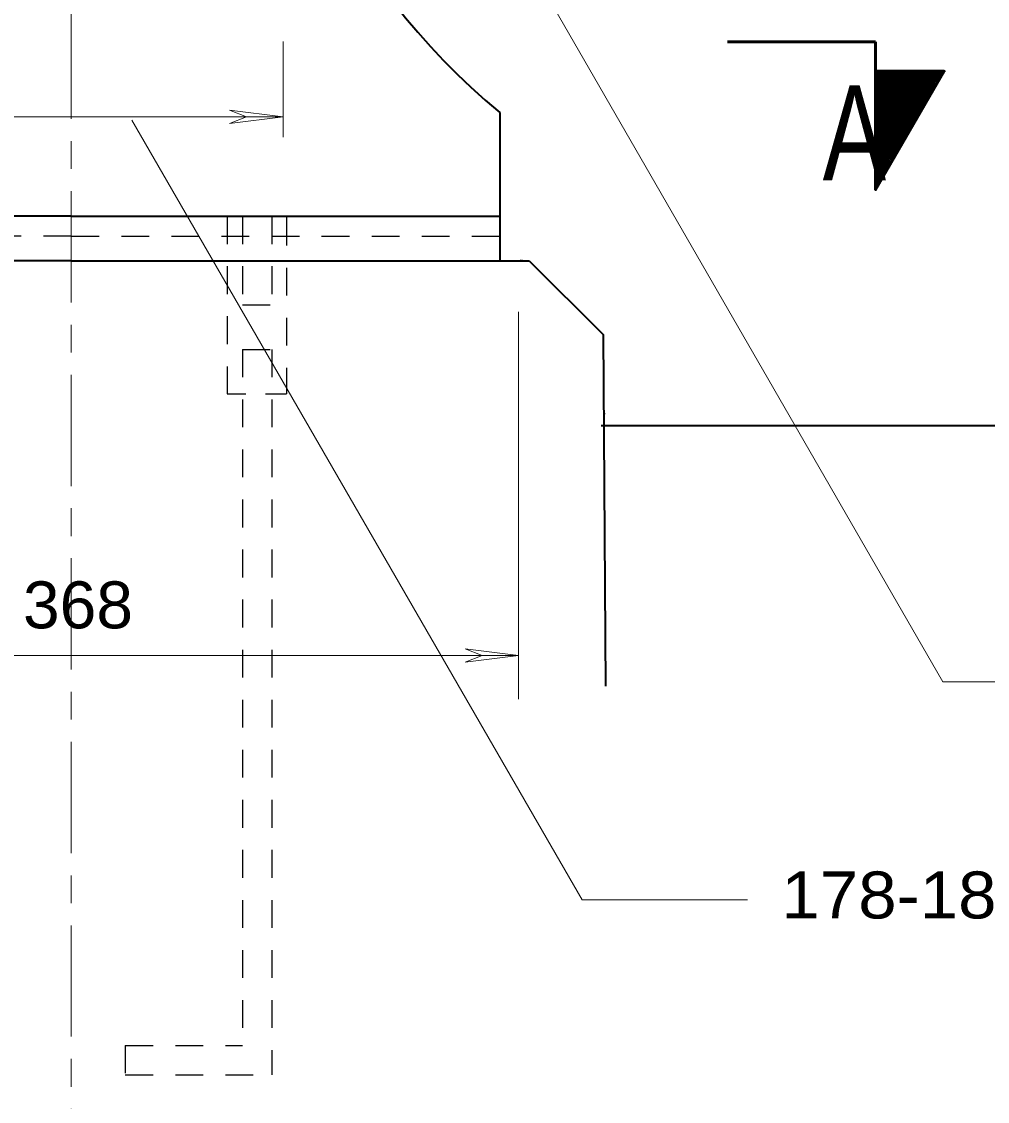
# Model space of a CAD drawing. Extents: x 312583 to 312854, y 144419 to 144597.
# Drawn here: x 312639.27 to 312654.89, y 144437.86 to 144455.33 of the extents above; entities that cross this region are included whole.
import ezdxf
from ezdxf.enums import TextEntityAlignment as Align

# ---------------------------------------------------------------- set-up
doc = ezdxf.new("R2010")
doc.units = 0
doc.header["$LTSCALE"] = 0.3
doc.linetypes.add('LONG_DASH_SHORT_DASH', pattern=[9.9, 6, -1.2, 1.5, -1.2])
doc.linetypes.add('SHORT_DASHED', pattern=[2.7, 1.5, -1.2])
doc.layers.add('1', color=7, linetype='Continuous', lineweight=40)
doc.layers.add('2', color=7, linetype='Continuous', lineweight=13)

msp = doc.modelspace()

# ---------------------------------------------------------------- linework, layer by layer
at = {"layer": '1', "linetype": 'LONG_DASH_SHORT_DASH', "lineweight": 13}
msp.add_line((312640.0738, 144435.9326), (312640.0738, 144549.4913), dxfattribs=at)
at = {"layer": '1'}
for p, q in [((312647.0045, 144453.8573), (312647.0045, 144451.4576)), ((312647.0045, 144453.8573), (312647.0045, 144451.4576)), ((312647.0045, 144453.8573), (312647.0045, 144451.4576)), ((312647.0045, 144453.8573), (312647.0045, 144451.4576)), ((312647.0045, 144453.8573), (312647.0045, 144451.4576)), ((312647.0045, 144453.8573), (312647.0045, 144451.4576)), ((312647.0045, 144453.8573), (312647.0045, 144451.4576)), ((312647.0045, 144453.8573), (312647.0045, 144451.4576)), ((312640.0738, 144452.1783), (312633.1432, 144452.1783)), ((312640.0738, 144452.1783), (312633.1432, 144452.1783)), ((312640.0738, 144452.1783), (312633.1432, 144452.1783)), ((312640.0738, 144452.1783), (312633.1432, 144452.1783)), ((312640.0738, 144452.1783), (312633.1432, 144452.1783)), ((312640.0738, 144452.1783), (312633.1432, 144452.1783)), ((312640.0738, 144452.1783), (312633.1432, 144452.1783)), ((312640.0738, 144452.1783), (312633.1432, 144452.1783)), ((312640.0738, 144452.1783), (312647.0045, 144452.1783)), ((312640.0738, 144452.1783), (312647.0045, 144452.1783)), ((312640.0738, 144452.1783), (312647.0045, 144452.1783)), ((312640.0738, 144452.1783), (312647.0045, 144452.1783)), ((312640.0738, 144452.1783), (312647.0045, 144452.1783)), ((312640.0738, 144452.1783), (312647.0045, 144452.1783)), ((312640.0738, 144452.1783), (312647.0045, 144452.1783)), ((312640.0738, 144452.1783), (312647.0045, 144452.1783)), ((312640.0738, 144451.4576), (312632.6755, 144451.4576)), ((312640.0738, 144451.4576), (312632.6755, 144451.4576)), ((312640.0738, 144451.4576), (312632.6755, 144451.4576)), ((312640.0738, 144451.4576), (312632.6755, 144451.4576)), ((312640.0738, 144451.4576), (312632.6755, 144451.4576)), ((312640.0738, 144451.4576), (312632.6755, 144451.4576)), ((312640.0738, 144451.4576), (312632.6755, 144451.4576)), ((312640.0738, 144451.4576), (312632.6755, 144451.4576)), ((312640.0738, 144451.4576), (312647.4798, 144451.4576)), ((312640.0738, 144451.4576), (312647.4798, 144451.4576)), ((312640.0738, 144451.4576), (312647.4798, 144451.4576)), ((312640.0738, 144451.4576), (312647.4798, 144451.4576)), ((312640.0738, 144451.4576), (312647.4798, 144451.4576)), ((312640.0738, 144451.4576), (312647.4798, 144451.4576)), ((312640.0738, 144451.4576), (312647.4798, 144451.4576)), ((312640.0738, 144451.4576), (312647.4798, 144451.4576)), ((312647.3495, 144451.4576), (312647.3418, 144451.4653)), ((312647.3495, 144451.4576), (312647.3418, 144451.4653)), ((312647.3495, 144451.4576), (312647.3418, 144451.4653)), ((312647.3495, 144451.4576), (312647.3418, 144451.4653)), ((312647.3495, 144451.4576), (312647.3418, 144451.4653)), ((312647.3495, 144451.4576), (312647.3418, 144451.4653)), ((312647.3495, 144451.4576), (312647.3418, 144451.4653)), ((312647.3495, 144451.4576), (312647.3418, 144451.4653)), ((312647.3725, 144451.4576), (312647.3648, 144451.4576)), ((312647.3725, 144451.4576), (312647.3648, 144451.4576)), ((312647.3725, 144451.4576), (312647.3648, 144451.4576)), ((312647.3725, 144451.4576), (312647.3648, 144451.4576)), ((312647.3725, 144451.4576), (312647.3648, 144451.4576)), ((312647.3725, 144451.4576), (312647.3648, 144451.4576)), ((312647.3725, 144451.4576), (312647.3648, 144451.4576)), ((312647.3725, 144451.4576), (312647.3648, 144451.4576)), ((312647.3725, 144451.4576), (312647.3648, 144451.4576)), ((312647.3725, 144451.4576), (312647.3648, 144451.4576)), ((312647.3725, 144451.4576), (312647.3648, 144451.4576)), ((312647.3725, 144451.4576), (312647.3648, 144451.4576)), ((312647.3725, 144451.4576), (312647.3648, 144451.4576)), ((312647.3725, 144451.4576), (312647.3648, 144451.4576)), ((312647.3725, 144451.4576), (312647.3648, 144451.4576)), ((312647.3725, 144451.4576), (312647.3648, 144451.4576)), ((312647.4798, 144451.4576), (312648.6758, 144450.2616)), ((312647.4798, 144451.4576), (312648.6758, 144450.2616)), ((312647.4798, 144451.4576), (312648.6758, 144450.2616)), ((312647.4798, 144451.4576), (312648.6758, 144450.2616)), ((312647.4798, 144451.4576), (312648.6758, 144450.2616)), ((312647.4798, 144451.4576), (312648.6758, 144450.2616)), ((312647.4798, 144451.4576), (312648.6758, 144450.2616)), ((312647.4798, 144451.4576), (312648.6758, 144450.2616)), ((312648.6758, 144450.2616), (312648.7142, 144444.5729)), ((312648.6758, 144450.2616), (312648.7142, 144444.5729)), ((312648.6758, 144450.2616), (312648.7142, 144444.5729)), ((312648.6758, 144450.2616), (312648.7142, 144444.5729)), ((312648.6758, 144450.2616), (312648.7142, 144444.5729)), ((312648.6758, 144450.2616), (312648.7142, 144444.5729)), ((312648.6758, 144450.2616), (312648.7142, 144444.5729)), ((312648.6758, 144450.2616), (312648.7142, 144444.5729)), ((312648.6988, 144448.9813), (312648.7065, 144448.9736)), ((312648.6988, 144448.9813), (312648.7065, 144448.9736)), ((312648.6988, 144448.9813), (312648.7065, 144448.9736)), ((312648.6988, 144448.9813), (312648.7065, 144448.9736)), ((312648.6988, 144448.9813), (312648.7065, 144448.9736)), ((312648.6988, 144448.9813), (312648.7065, 144448.9736)), ((312648.6988, 144448.9813), (312648.7065, 144448.9736)), ((312648.6988, 144448.9813), (312648.7065, 144448.9736)), ((312648.6452, 144448.7896), (312660.3062, 144448.7896)), ((312648.6452, 144448.7896), (312660.3062, 144448.7896)), ((312648.6452, 144448.7896), (312660.3062, 144448.7896)), ((312648.6452, 144448.7896), (312660.3062, 144448.7896)), ((312648.6452, 144448.7896), (312660.3062, 144448.7896)), ((312648.6452, 144448.7896), (312660.3062, 144448.7896)), ((312648.6452, 144448.7896), (312660.3062, 144448.7896)), ((312648.6452, 144448.7896), (312660.3062, 144448.7896))]:
    msp.add_line(p, q, dxfattribs=at)
at = {"layer": '1', "linetype": 'SHORT_DASHED', "lineweight": 25}
for p, q in [((312642.5962, 144452.1783), (312642.5962, 144449.3033)), ((312642.5962, 144452.1783), (312642.5962, 144449.3033)), ((312642.5962, 144452.1783), (312642.5962, 144449.3033)), ((312642.5962, 144452.1783), (312642.5962, 144449.3033)), ((312642.5962, 144452.1783), (312642.5962, 144449.3033)), ((312642.5962, 144452.1783), (312642.5962, 144449.3033)), ((312642.5962, 144452.1783), (312642.5962, 144449.3033)), ((312642.5962, 144452.1783), (312642.5962, 144449.3033)), ((312642.8415, 144452.1783), (312642.8415, 144450.7446)), ((312642.8415, 144452.1783), (312642.8415, 144450.7446)), ((312642.8415, 144452.1783), (312642.8415, 144450.7446)), ((312642.8415, 144452.1783), (312642.8415, 144450.7446)), ((312642.8415, 144452.1783), (312642.8415, 144450.7446)), ((312642.8415, 144452.1783), (312642.8415, 144450.7446)), ((312642.8415, 144452.1783), (312642.8415, 144450.7446)), ((312642.8415, 144452.1783), (312642.8415, 144450.7446)), ((312643.3168, 144452.1783), (312643.3168, 144450.7446)), ((312643.3168, 144452.1783), (312643.3168, 144450.7446)), ((312643.3168, 144452.1783), (312643.3168, 144450.7446)), ((312643.3168, 144452.1783), (312643.3168, 144450.7446)), ((312643.3168, 144452.1783), (312643.3168, 144450.7446)), ((312643.3168, 144452.1783), (312643.3168, 144450.7446)), ((312643.3168, 144452.1783), (312643.3168, 144450.7446)), ((312643.3168, 144452.1783), (312643.3168, 144450.7446)), ((312643.5545, 144452.1553), (312643.5545, 144449.3033)), ((312643.5545, 144452.1553), (312643.5545, 144449.3033)), ((312643.5545, 144452.1553), (312643.5545, 144449.3033)), ((312643.5545, 144452.1553), (312643.5545, 144449.3033)), ((312643.5545, 144452.1553), (312643.5545, 144449.3033)), ((312643.5545, 144452.1553), (312643.5545, 144449.3033)), ((312643.5545, 144452.1553), (312643.5545, 144449.3033)), ((312643.5545, 144452.1553), (312643.5545, 144449.3033)), ((312640.0738, 144451.8563), (312633.1432, 144451.8563)), ((312640.0738, 144451.8563), (312633.1432, 144451.8563)), ((312640.0738, 144451.8563), (312633.1432, 144451.8563)), ((312640.0738, 144451.8563), (312633.1432, 144451.8563)), ((312640.0738, 144451.8563), (312633.1432, 144451.8563)), ((312640.0738, 144451.8563), (312633.1432, 144451.8563)), ((312640.0738, 144451.8563), (312633.1432, 144451.8563)), ((312640.0738, 144451.8563), (312633.1432, 144451.8563)), ((312640.0738, 144451.8563), (312647.0045, 144451.8563)), ((312640.0738, 144451.8563), (312647.0045, 144451.8563)), ((312640.0738, 144451.8563), (312647.0045, 144451.8563)), ((312640.0738, 144451.8563), (312647.0045, 144451.8563)), ((312640.0738, 144451.8563), (312647.0045, 144451.8563)), ((312640.0738, 144451.8563), (312647.0045, 144451.8563)), ((312640.0738, 144451.8563), (312647.0045, 144451.8563)), ((312640.0738, 144451.8563), (312647.0045, 144451.8563)), ((312642.8415, 144450.7446), (312643.3168, 144450.7446)), ((312642.8415, 144450.7446), (312643.3168, 144450.7446)), ((312642.8415, 144450.7446), (312643.3168, 144450.7446)), ((312642.8415, 144450.7446), (312643.3168, 144450.7446)), ((312642.8415, 144450.7446), (312643.3168, 144450.7446)), ((312642.8415, 144450.7446), (312643.3168, 144450.7446)), ((312642.8415, 144450.7446), (312643.3168, 144450.7446)), ((312642.8415, 144450.7446), (312643.3168, 144450.7446)), ((312642.8415, 144450.0239), (312643.3168, 144450.0239)), ((312642.8415, 144450.0239), (312642.8415, 144438.7616)), ((312642.8415, 144450.0239), (312643.3168, 144450.0239)), ((312642.8415, 144450.0239), (312642.8415, 144438.7616)), ((312642.8415, 144450.0239), (312643.3168, 144450.0239)), ((312642.8415, 144450.0239), (312642.8415, 144438.7616)), ((312642.8415, 144450.0239), (312643.3168, 144450.0239)), ((312642.8415, 144450.0239), (312642.8415, 144438.7616)), ((312642.8415, 144450.0239), (312643.3168, 144450.0239)), ((312642.8415, 144450.0239), (312642.8415, 144438.7616)), ((312642.8415, 144450.0239), (312643.3168, 144450.0239)), ((312642.8415, 144450.0239), (312642.8415, 144438.7616)), ((312642.8415, 144450.0239), (312643.3168, 144450.0239)), ((312642.8415, 144450.0239), (312642.8415, 144438.7616)), ((312642.8415, 144450.0239), (312643.3168, 144450.0239)), ((312642.8415, 144450.0239), (312642.8415, 144438.7616)), ((312643.3168, 144450.0239), (312643.3168, 144438.2863)), ((312643.3168, 144450.0239), (312643.3168, 144438.2863)), ((312643.3168, 144450.0239), (312643.3168, 144438.2863)), ((312643.3168, 144450.0239), (312643.3168, 144438.2863)), ((312643.3168, 144450.0239), (312643.3168, 144438.2863)), ((312643.3168, 144450.0239), (312643.3168, 144438.2863)), ((312643.3168, 144450.0239), (312643.3168, 144438.2863)), ((312643.3168, 144450.0239), (312643.3168, 144438.2863)), ((312642.5962, 144449.3033), (312642.8952, 144449.3033)), ((312642.5962, 144449.3033), (312642.8952, 144449.3033)), ((312642.5962, 144449.3033), (312642.8952, 144449.3033)), ((312642.5962, 144449.3033), (312642.8952, 144449.3033)), ((312642.5962, 144449.3033), (312642.8952, 144449.3033)), ((312642.5962, 144449.3033), (312642.8952, 144449.3033)), ((312642.5962, 144449.3033), (312642.8952, 144449.3033)), ((312642.5962, 144449.3033), (312642.8952, 144449.3033)), ((312643.2172, 144449.3033), (312643.5545, 144449.3033)), ((312643.2172, 144449.3033), (312643.5545, 144449.3033)), ((312643.2172, 144449.3033), (312643.5545, 144449.3033)), ((312643.2172, 144449.3033), (312643.5545, 144449.3033)), ((312643.2172, 144449.3033), (312643.5545, 144449.3033)), ((312643.2172, 144449.3033), (312643.5545, 144449.3033)), ((312643.2172, 144449.3033), (312643.5545, 144449.3033)), ((312643.2172, 144449.3033), (312643.5545, 144449.3033)), ((312640.9478, 144438.7616), (312642.8415, 144438.7616)), ((312640.9478, 144438.7616), (312640.9478, 144438.2863)), ((312640.9478, 144438.7616), (312642.8415, 144438.7616)), ((312640.9478, 144438.7616), (312640.9478, 144438.2863)), ((312640.9478, 144438.7616), (312642.8415, 144438.7616)), ((312640.9478, 144438.7616), (312640.9478, 144438.2863)), ((312640.9478, 144438.7616), (312642.8415, 144438.7616)), ((312640.9478, 144438.7616), (312640.9478, 144438.2863)), ((312640.9478, 144438.7616), (312642.8415, 144438.7616)), ((312640.9478, 144438.7616), (312640.9478, 144438.2863)), ((312640.9478, 144438.7616), (312642.8415, 144438.7616)), ((312640.9478, 144438.7616), (312640.9478, 144438.2863)), ((312640.9478, 144438.7616), (312642.8415, 144438.7616)), ((312640.9478, 144438.7616), (312640.9478, 144438.2863)), ((312640.9478, 144438.7616), (312642.8415, 144438.7616)), ((312640.9478, 144438.7616), (312640.9478, 144438.2863)), ((312640.9478, 144438.2863), (312643.3168, 144438.2863)), ((312640.9478, 144438.2863), (312643.3168, 144438.2863)), ((312640.9478, 144438.2863), (312643.3168, 144438.2863)), ((312640.9478, 144438.2863), (312643.3168, 144438.2863)), ((312640.9478, 144438.2863), (312643.3168, 144438.2863)), ((312640.9478, 144438.2863), (312643.3168, 144438.2863)), ((312640.9478, 144438.2863), (312643.3168, 144438.2863)), ((312640.9478, 144438.2863), (312643.3168, 144438.2863))]:
    msp.add_line(p, q, dxfattribs=at)
at = {"layer": '1'}
msp.add_arc((312654.0635, 144462.3949), 11.0776, 179.55818, 230.43377, dxfattribs=at)
msp.add_arc((312654.0635, 144462.3949), 11.0776, 179.55818, 230.43377, dxfattribs=at)
msp.add_arc((312654.0635, 144462.3949), 11.0776, 179.55818, 230.43377, dxfattribs=at)
msp.add_arc((312654.0635, 144462.3949), 11.0776, 179.55818, 230.43377, dxfattribs=at)
msp.add_arc((312654.0635, 144462.3949), 11.0776, 179.55818, 230.43377, dxfattribs=at)
msp.add_arc((312654.0635, 144462.3949), 11.0776, 179.55818, 230.43377, dxfattribs=at)
msp.add_arc((312654.0635, 144462.3949), 11.0776, 179.55818, 230.43377, dxfattribs=at)
msp.add_arc((312654.0635, 144462.3949), 11.0776, 179.55818, 230.43377, dxfattribs=at)
at = {"layer": '2'}
for p, q in [((312647.7865, 144455.7203), (312654.1728, 144444.6419)), ((312643.5008, 144455.0073), (312643.5008, 144453.4586)), ((312642.6345, 144453.8956), (312642.9105, 144453.7883)), ((312643.5008, 144453.7883), (312642.6345, 144453.8956)), ((312636.8155, 144453.7883), (312643.5008, 144453.7883)), ((312641.0552, 144453.7346), (312648.3385, 144441.1153)), ((312642.6345, 144453.6809), (312642.9105, 144453.7883)), ((312643.5008, 144453.7883), (312642.6345, 144453.6809)), ((312647.3112, 144444.3659), (312647.3112, 144450.6296)), ((312647.3112, 144445.0713), (312633.0895, 144445.0713)), ((312646.4448, 144445.1786), (312646.7208, 144445.0713)), ((312647.3112, 144445.0713), (312646.4448, 144445.1786)), ((312646.4448, 144444.9639), (312646.7208, 144445.0713)), ((312647.3112, 144445.0713), (312646.4448, 144444.9639)), ((312657.8222, 144444.6419), (312654.1728, 144444.6419)), ((312651.0108, 144441.1153), (312648.3385, 144441.1153))]:
    msp.add_line(p, q, dxfattribs=at)
at = {"layer": '2', "lineweight": 53}
for p in [(312650.6922, 144454.9996), (312653.0842, 144454.5243)]:
    msp.add_line(p, (312653.0842, 144454.9996), dxfattribs=at)
at = {"layer": '2', "lineweight": 35}
for p, q in [((312653.0842, 144454.5089), (312653.9045, 144454.0336)), ((312653.1072, 144454.5243), (312653.9198, 144454.0489)), ((312653.1608, 144454.5243), (312653.9275, 144454.0796)), ((312653.1992, 144454.5243), (312653.9428, 144454.0949)), ((312653.2528, 144454.5243), (312653.9505, 144454.1179)), ((312653.2988, 144454.5243), (312653.9658, 144454.1409)), ((312653.3448, 144454.5243), (312653.9812, 144454.1563)), ((312653.3908, 144454.5243), (312653.9888, 144454.1793)), ((312653.4445, 144454.5243), (312654.0042, 144454.2023)), ((312653.4905, 144454.5243), (312654.0195, 144454.2176)), ((312653.5365, 144454.5243), (312654.0272, 144454.2406)), ((312653.5902, 144454.5243), (312654.0425, 144454.2559)), ((312653.6362, 144454.5243), (312654.0502, 144454.2789)), ((312653.6822, 144454.5243), (312654.0655, 144454.3019)), ((312653.7358, 144454.5243), (312654.0732, 144454.3173)), ((312653.7818, 144454.5243), (312654.0885, 144454.3479)), ((312653.8278, 144454.5243), (312654.0962, 144454.3633)), ((312653.8738, 144454.5243), (312654.1115, 144454.3863)), ((312653.9275, 144454.5243), (312654.1192, 144454.4093)), ((312653.9658, 144454.5243), (312654.1345, 144454.4246)), ((312654.0195, 144454.5243), (312654.1422, 144454.4476)), ((312654.0655, 144454.5243), (312654.1575, 144454.4706)), ((312654.1192, 144454.5243), (312654.1728, 144454.4859)), ((312654.1652, 144454.5243), (312654.1805, 144454.5089)), ((312653.0842, 144454.4783), (312653.8968, 144454.0106)), ((312653.0842, 144454.4476), (312653.8815, 144453.9876)), ((312653.0842, 144454.4246), (312653.8738, 144453.9723)), ((312653.0842, 144454.3939), (312653.8585, 144453.9493)), ((312653.0918, 144454.3709), (312653.8508, 144453.9263)), ((312653.0918, 144454.3403), (312653.8355, 144453.9109)), ((312653.0842, 144454.3173), (312653.8278, 144453.8879)), ((312653.0842, 144454.2866), (312653.8125, 144453.8649)), ((312653.0842, 144454.2559), (312653.7972, 144453.8496)), ((312653.0842, 144454.2329), (312653.7895, 144453.8266)), ((312653.0842, 144454.2023), (312653.7742, 144453.8036)), ((312653.0842, 144454.1716), (312653.7588, 144453.7806)), ((312653.0842, 144454.1486), (312653.7512, 144453.7653)), ((312653.0842, 144454.0873), (312653.7282, 144453.7193)), ((312653.0842, 144454.0643), (312653.7128, 144453.7039)), ((312653.0842, 144454.0413), (312653.7052, 144453.6809)), ((312653.0842, 144454.0106), (312653.6898, 144453.6579)), ((312653.0842, 144453.9799), (312653.6822, 144453.6426)), ((312653.0918, 144454.1179), (312653.7358, 144453.7423)), ((312653.0842, 144453.9493), (312653.6668, 144453.6196)), ((312653.0842, 144453.9263), (312653.6592, 144453.5966)), ((312653.0842, 144453.8956), (312653.6438, 144453.5813)), ((312653.0842, 144453.8419), (312653.6208, 144453.5353)), ((312653.0842, 144453.8189), (312653.6055, 144453.5123)), ((312653.0918, 144453.8726), (312653.6362, 144453.5506)), ((312653.0842, 144453.7883), (312653.5978, 144453.4893)), ((312653.0842, 144453.7576), (312653.5825, 144453.4739)), ((312653.0842, 144453.7346), (312653.5748, 144453.4509)), ((312653.0842, 144453.7039), (312653.5595, 144453.4279)), ((312653.0842, 144453.6733), (312653.5518, 144453.4126)), ((312653.0842, 144453.6503), (312653.5365, 144453.3896)), ((312653.0842, 144453.6196), (312653.5288, 144453.3666)), ((312653.0842, 144453.5889), (312653.5135, 144453.3513)), ((312653.0842, 144453.5659), (312653.5058, 144453.3283)), ((312653.0842, 144453.5429), (312653.4905, 144453.3053)), ((312653.0842, 144453.5123), (312653.4828, 144453.2823)), ((312653.0842, 144453.4816), (312653.4675, 144453.2669)), ((312653.0842, 144453.4509), (312653.4522, 144453.2439)), ((312653.0842, 144453.4279), (312653.4445, 144453.2209)), ((312653.0842, 144453.3973), (312653.4292, 144453.2056)), ((312653.0842, 144453.3743), (312653.4138, 144453.1826)), ((312653.0842, 144453.3436), (312653.4062, 144453.1596)), ((312653.0842, 144453.3206), (312653.3908, 144453.1443)), ((312653.0842, 144453.2899), (312653.3832, 144453.1213)), ((312653.0842, 144453.2593), (312653.3678, 144453.0983)), ((312653.0842, 144453.2363), (312653.3602, 144453.0829)), ((312653.0842, 144453.2056), (312653.3448, 144453.0523)), ((312653.0842, 144453.1826), (312653.3372, 144453.0369)), ((312653.0842, 144453.1519), (312653.3218, 144453.0139)), ((312653.0842, 144453.1213), (312653.3142, 144452.9909)), ((312653.0842, 144453.0983), (312653.2988, 144452.9756)), ((312653.0842, 144453.0676), (312653.2912, 144452.9526)), ((312653.0842, 144453.0446), (312653.2758, 144452.9296)), ((312653.0842, 144453.0139), (312653.2605, 144452.9143)), ((312653.0842, 144452.9833), (312653.2528, 144452.8913)), ((312653.0842, 144452.9526), (312653.2375, 144452.8683)), ((312653.0842, 144452.9296), (312653.2222, 144452.8529)), ((312653.0842, 144452.8989), (312653.2145, 144452.8299)), ((312653.0842, 144452.8759), (312653.1992, 144452.8069)), ((312653.0842, 144452.8529), (312653.1915, 144452.7839)), ((312653.0842, 144452.8223), (312653.1762, 144452.7686)), ((312653.0842, 144452.7916), (312653.1685, 144452.7456)), ((312653.0842, 144452.7609), (312653.1532, 144452.7226)), ((312653.0842, 144452.7379), (312653.1455, 144452.7073)), ((312653.0842, 144452.7073), (312653.1302, 144452.6843)), ((312653.0842, 144452.6843), (312653.1225, 144452.6613)), ((312653.0842, 144452.6536), (312653.1072, 144452.6459)), ((312653.0842, 144452.6229), (312653.0995, 144452.6229))]:
    msp.add_line(p, q, dxfattribs=at)
at = {"layer": '2', "lineweight": 53}
msp.add_lwpolyline([(312653.0842, 144454.5243), (312654.1958, 144454.5243), (312653.0842, 144452.6076)], close=True, dxfattribs=at)

# ---------------------------------------------------------------- texts
at = {"layer": '2', "width": 0.75}
msp.add_text('A', height=1.533, dxfattribs=at).set_placement((312652.743, 144452.7609), align=Align.CENTER)
at = {"layer": '2'}
for s, width, p in [('368', 1.05, (312639.2918, 144445.5096)), ('178-187', 1.1, (312651.5608, 144440.8153))]:
    msp.add_text(s, height=0.76, dxfattribs=dict(at, width=width)).set_placement(p)

doc.saveas('drawing.dxf')
